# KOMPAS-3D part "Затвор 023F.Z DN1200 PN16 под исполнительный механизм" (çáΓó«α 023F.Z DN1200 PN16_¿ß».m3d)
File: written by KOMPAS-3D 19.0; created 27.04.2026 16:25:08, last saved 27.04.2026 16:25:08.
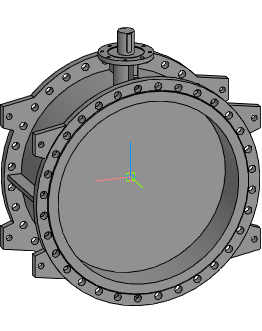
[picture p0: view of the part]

Document properties: Автор: Евгений; Полное имя файла: Z:\3.Личные\kachalov\3d для проектировщиков\1.7 Тип 023F.Z Затвор дисковый поворотный фланцевый с двумя эксцентриками\Затвор 023F.Z DN200-DN1600_исп\_stp_Затвор 023F.Z DN200-DN1600_исп\Затвор 023F.Z DN1200 PN16_исп.m3d

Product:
- Part/product: Затвор 023F.Z DN1200 PN16 под исполнительный механизм

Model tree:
1. Операция без истории:1  (labels: Затвор 023F.Z DN1200 PN16 под исполнительный механизм)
